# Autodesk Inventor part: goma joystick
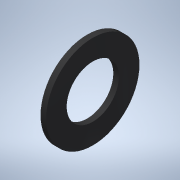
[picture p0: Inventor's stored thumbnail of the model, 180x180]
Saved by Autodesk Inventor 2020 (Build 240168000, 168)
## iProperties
Created: 2018-10
Part Number: goma joystick
Material: Genérico
Document SubType Name: Modeling
Designer: Pedro
Density: 1 g/cm^3
Appearance: Por defecto
Author: Pedro
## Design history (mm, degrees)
sketch "Boceto1"
  geometry: C1 r 25 at (-3.431, 2.656); C2 r 14 at (-3.431, 2.656); 1 further point
  constraints: 2 centre point, 1 coincident
  dimensions: "d0" = 50 diameter of C1; "d1" = 28 diameter of C2
extrude "Extrusión1" new body sketch "Boceto1" distance "d2" = 3; taper "d3" = 0 deg
node "Sólido1"
